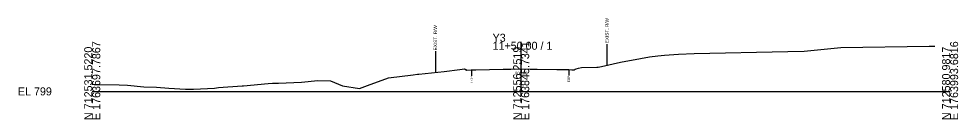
# Model space of a CAD drawing. Extents: x -26 to 2903, y -10 to 5022.
# Drawn here: x -25.7 to 302.8, y 1490.3 to 1525.3 of the extents above; entities that cross this region are included whole.
import ezdxf

# ---------------------------------------------------------------- set-up
doc = ezdxf.new("R2010")
doc.units = 0
for name, color, linetype in [('Default', 7, 'Continuous'), ('Exist Cross Section Cell', 7, 'Continuous'), ('Exist XS Center Line Elevation Label', 7, 'Continuous'), ('Exist XS Ground Line', 7, 'Continuous'), ('Old_Level_10', 7, 'Continuous')]:
    doc.layers.add(name, color=color, linetype=linetype)

msp = doc.modelspace()

# ---------------------------------------------------------------- linework, layer by layer
at = {"layer": 'Exist Cross Section Cell'}
for p, q in [((150, 1500), (150, 1517.32)), ((0, 1500), (150, 1500)), ((150, 1500), (300, 1500))]:
    msp.add_line(p, q, dxfattribs=at)
at = {"layer": 'Exist XS Ground Line'}
for points in [[(0, 1502.52), (2.19, 1502.4), (9.38, 1502.34), (12.33, 1502.2), (18.07, 1501.6), (22.47, 1501.43), (26.75, 1501.09), (32.61, 1500.79), (35.44, 1500.77), (42.75, 1501.11), (44.13, 1501.36), (52.4, 1501.89), (52.82, 1501.91), (52.89, 1501.92), (61.51, 1502.79), (63.03, 1502.84), (65.16, 1502.86), (73.17, 1503.26), (78.88, 1503.77), (83.31, 1503.65), (87.57, 1501.92), (93.45, 1501.01), (96.26, 1502.01), (103.59, 1504.69), (112.23, 1505.79), (113.77, 1506), (114.21, 1506.05), (123.08, 1506.92), (128.53, 1507.66), (130.23, 1507.92), (130.85, 1507.47), (130.92, 1507.42), (132.54, 1507.51), (132.73, 1507.53), (134.12, 1507.55), (143.72, 1507.73), (146.38, 1507.79), (149.98, 1507.86), (150, 1507.86), (153.17, 1507.79), (155.6, 1507.74), (162.47, 1507.66), (166.64, 1507.61), (167.73, 1507.53), (168.52, 1507.47), (168.93, 1507.73), (169.2, 1507.91), (169.99, 1508.13), (171.06, 1508.36), (176.41, 1508.44), (176.97, 1508.45), (178.12, 1508.69), (184.74, 1510.14), (191.71, 1511.5), (194.88, 1512.02), (197.85, 1512.35), (200.11, 1512.6), (205.02, 1512.99), (210.5, 1513.22), (243.24, 1513.86), (249.01, 1514.02), (261.84, 1515.34), (292.72, 1515.83), (294.71, 1515.76)], [(0, 1502.52), (2.19, 1502.4), (9.38, 1502.34), (12.33, 1502.2), (18.07, 1501.6), (22.47, 1501.43), (26.75, 1501.09), (32.61, 1500.79), (35.44, 1500.77), (42.75, 1501.11), (44.13, 1501.36), (52.4, 1501.89), (52.89, 1501.92), (61.51, 1502.79), (63.03, 1502.84), (65.16, 1502.86), (73.17, 1503.26), (78.88, 1503.77), (83.31, 1503.65), (87.57, 1501.92), (93.45, 1501.01), (96.26, 1502.01), (103.59, 1504.69), (112.23, 1505.79), (113.77, 1506), (114.21, 1506.05), (123.08, 1506.92), (128.53, 1507.66), (130.23, 1507.92), (130.92, 1507.42), (132.73, 1507.53), (134.12, 1507.55), (143.72, 1507.73), (146.38, 1507.79), (149.98, 1507.86), (153.17, 1507.79), (155.6, 1507.74), (162.47, 1507.66), (166.64, 1507.61), (167.73, 1507.53), (168.52, 1507.47), (169.2, 1507.91), (169.99, 1508.13), (171.06, 1508.36), (176.41, 1508.44), (176.97, 1508.45), (178.12, 1508.69), (184.74, 1510.14), (191.71, 1511.5), (194.88, 1512.02), (197.85, 1512.35), (200.11, 1512.6), (205.02, 1512.99), (210.5, 1513.22), (243.24, 1513.86), (249.01, 1514.02), (261.84, 1515.34), (292.72, 1515.83), (294.71, 1515.76)]]:
    msp.add_lwpolyline(points, dxfattribs=at)
at = {"layer": 'Old_Level_10'}
for p, q in [((180, 1516.51), (180, 1509.1)), ((120, 1514.02), (120, 1506.62)), ((132.68, 1507.52), (132.68, 1505.47)), ((166.68, 1507.61), (166.68, 1505.56))]:
    msp.add_line(p, q, dxfattribs=at)

# ---------------------------------------------------------------- texts
at = {"layer": 'Default'}
msp.add_text('-', height=0.0001, dxfattribs=at).set_placement((0, 1500))
at = {"layer": 'Exist Cross Section Cell'}
for s, p in [('Y3', (140, 1517.32)), ('11+50.00 / 1', (140, 1514.52)), ('EL 799', (-26, 1498.6))]:
    msp.add_text(s, height=2.8, dxfattribs=at).set_placement(p)
for s, p in [('N 712531.5220', (0, 1490)), ('E 1763697.7867', (2.8, 1490)), ('N 712556.2519', (150, 1490)), ('E 1763845.7341', (152.8, 1490)), ('N 712580.9817', (300, 1490)), ('E 1763993.6816', (302.8, 1490))]:
    msp.add_text(s, height=2.8, rotation=90, dxfattribs=at).set_placement(p)
at = {"layer": 'Exist XS Center Line Elevation Label'}
msp.add_text('806.86', height=1, dxfattribs=at).set_placement((147.86, 1505.86))
at = {"layer": 'Old_Level_10'}
for s, height, p in [('EXIST. R/W', 1.181, (180.59, 1516.81)), ('EXIST. R/W', 1.181, (120.59, 1514.32)), ('EOP', 0.787, (133.08, 1503.08)), ('EOP', 0.787, (167.07, 1503.16))]:
    msp.add_text(s, height=height, rotation=90, dxfattribs=at).set_placement(p)

doc.saveas('drawing.dxf')
